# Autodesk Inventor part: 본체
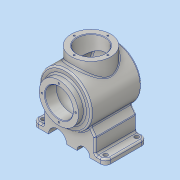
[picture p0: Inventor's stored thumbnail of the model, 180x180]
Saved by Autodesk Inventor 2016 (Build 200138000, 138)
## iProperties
Created: 2018-08
Part Number: 본체
Material: 알루미늄 6061
Document SubType Name: Modeling
Designer: 605-07
Density: 2.7 g/cm^3
Appearance: 알루미늄 - 평지
Author: 605-07
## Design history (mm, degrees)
sketch "스케치1"
  geometry: L1 (70, 40)-(-70, 40); L2 (-70, 40)-(-70, -40); L3 (-70, -40)-(70, -40); L4 (70, -40)-(70, 40); L5 (70, 40)-(-70, -40); L6 (-70, 40)-(70, -40); 1 further point
  constraints: 12 end point, 2 midpoint, 2 parallel, 1 horizontal, 1 perpendicular
  dimensions: "d0" = 140 distance of L1.start L1.end; "d1" = 80 distance of L1.end L2.end
extrude "돌출1" new body sketch "스케치1" distance "d2" = 10; taper "d3" = 0 deg
fillet "모깎기1" dims "d4" = 10
sketch "스케치2"
  geometry: L1 (120, 10)-(0, 10) reference; L2 (10, 10)-(10, 38.563); L3 (-10, 10)-(-10, 0) reference; L4 (110, 10)-(110, 38.563); L5 (130, 0)-(130, 10) reference; L6 (10, 38.563)-(60, 109.97); L7 (110, 38.563)-(60, 109.97); L8 (-10, 0)-(-10, 10) reference; L9 (10, 38.563)-(-10, 10); L10 (110, 38.563)-(130, 10); L11 (10, 10)-(110, 10); 1 further point
  constraints: 14 end point, 3 point on line, 2 collinear, 2 vertical, 1 perpendicular
  dimensions: "d5" = 20 distance between parallel lines of L2 L3; "d6" = 20 distance between parallel lines of L5 L4; "d7" = 35 deg angle of L3 L6; "d8" = 35 deg angle of L5 L7
extrude "돌출2" join sketch "스케치2" distance "d9" = 80; taper "d10" = 0 deg
node "작업 평면1"
sketch "스케치3"
  geometry: C1 r 50 at (60, 82); 1 further point
  constraints: 1 centre point, 1 vertical alignment
  dimensions: "d12" = 82 distance of C1.centre point (60, 0); "d13" = 100 diameter of C1
extrude "돌출3" join sketch "스케치3" distance "d14" = 108; taper "d15" = 0 deg
sketch "스케치4"
  geometry: L1 (32, -60)-(132, -60) reference; L2 (32, 48)-(132, 48) reference; L3 (82, 56)-(82, -60); L4 (82, -60)-(132, -60); L5 (132, -60)-(132, -48.671); A1 r 116 centre (82, 56) between (82, -60) and (132, -48.671); 2 further points
  constraints: 6 end point, 2 midpoint, 2 point on circle, 1 centre point, 1 horizontal, 1 perpendicular, 1 tangent, 1 vertical, 1 vertical alignment
  dimensions: "d16" = 116 radius of A1; "d17" = 50 distance of L3.end L4.end
revolve "회전1" sketch "스케치4" stored, may be unused: angle "d18" = 90 deg
sketch "스케치5"
  geometry: C1 r 50 at (0, 0) reference; C2 r 38 at (0, 0); 1 further point
  constraints: 1 centre point, 1 coincident
  dimensions: "d19" = 76 diameter of C2
extrude "돌출4" join sketch "스케치5" distance "d20" = 12; taper "d21" = 0 deg
sketch "스케치6"
  geometry: L1 (120, 0)-(0, 0) reference; C1 r 17.5 at (37.5, 0); C2 r 12.5 at (87.5, 0); 1 further point
  constraints: 2 centre point, 2 point on line
  dimensions: "d22" = 22.5 distance of point (60, 0) C1.centre; "d23" = 17.5 radius of C1; "d24" = 27.5 distance of C2.centre point (60, 0); "d25" = 12.5 radius of C2
extrude "돌출5" cut sketch "스케치6" stored distance "d26" = 12; taper "d27" = 0 deg
sketch "스케치7"
  geometry: C1 r 38 at (0, 0) reference; C2 r 27 at (0, 0); 1 further point
  constraints: 1 centre point, 1 coincident
  dimensions: "d28" = 54 diameter of C2
extrude "돌출6" cut sketch "스케치7" distance "d29" = 22; taper "d30" = 0 deg
sketch "스케치8"
  geometry: L1 (122, 38)-(82, 38); L2 (82, 38)-(82, -50); L3 (122, -42.163)-(122, 38); L4 (55, 38)-(109, 38) reference; L5 (132, 48)-(132, -48.671) reference; A1 r 116 centre (82, 56) between (32, -48.671) and (132, -48.671) reference; A2 r 106 centre (82, 56) between (82, -50) and (122, -42.163); 1 further point
  constraints: 6 end point, 2 point on circle, 1 centre point, 1 collinear, 1 horizontal, 1 parallel, 1 perpendicular
  dimensions: "d31" = 10 distance between parallel lines of L3 L5; "d32" = 40 distance between parallel lines of L2 L3; "d33" = 10 radial gap between concentric circles of A1 A2
revolve "회전2" sketch "스케치8" stored, may be unused: angle "d34" = 90 deg
node "작업 평면2"
sketch "스케치9"
  geometry: L1 (-50, 48)-(50, 48) reference; C1 r 38 at (0, -2); 1 further point
  constraints: 1 centre point, 1 vertical alignment
  dimensions: "d36" = 50 distance from line of L1 C1.centre; "d37" = 76 diameter of C1
extrude "돌출7" join sketch "스케치9" stored distance "d38" = 22; taper "d39" = 0 deg
sketch "스케치10"
  geometry: C1 r 38 at (0, 0) reference; C2 r 27 at (0, 0); 1 further point
  constraints: 1 centre point, 1 coincident
  dimensions: "d40" = 54 diameter of C2
extrude "돌출8" cut sketch "스케치10" stored distance "d41" = 22; taper "d42" = 0 deg
sketch "스케치11"
  geometry: C1 r 27 at (0, 0) reference; 2 further points
  constraints: 1 vertical alignment
  dimensions: "d43" = 32.5 distance of C1.centre point (0, 32.5)
hole "구멍1" sketch "스케치11" at (0, 32.5) diameter "d44" = 3.242; stored, may be unused: countersink angle "d48" = 90 deg, drill point angle "d50" = 118 deg; dims "d45" = 8, "d46" = 4, "d47" = 2, "d49" = 10
sketch "스케치12"
  geometry: C1 r 27 at (0, 0) reference; 2 further points
  constraints: 1 vertical alignment
  dimensions: "d54" = 32.5 distance of C1.centre point (0, 32.5)
hole "구멍2" sketch "스케치12" at (0, 32.5) diameter "d55" = 3.242; stored, may be unused: countersink angle "d59" = 90 deg, drill point angle "d61" = 118 deg; dims "d56" = 8, "d57" = 4, "d58" = 2, "d60" = 10
fillet "모깎기3" dims "d66" = 3
fillet "모깎기4" dims "d67" = 3
chamfer "모따기1" distance "d68" = 1; stored, may be unused: second distance "d69" = 2, angle "d70" = 45 deg
sketch "스케치15"
  geometry: L1 (-70, 30)-(-67, 30) reference; L2 (70, 30)-(67, 30) reference; L3 (70, -30)-(67, -30) reference; L4 (-60, -40)-(-60, -37) reference; L5 (-70, -30)-(-67, -30) reference; L6 (60, -40)-(60, -37) reference; L7 (60, 40)-(60, 37) reference; L8 (-60, 40)-(-60, 37) reference; A1 r 7 centre (-60, 30) between (-60, 37) and (-67, 30) reference; A2 r 10 centre (-60, 30) between (-60, 40) and (-70, 30) reference; A3 r 7 centre (60, 30) between (67, 30) and (60, 37) reference; A4 r 10 centre (60, 30) between (70, 30) and (60, 40) reference; A5 r 7 centre (60, -30) between (60, -37) and (67, -30) reference; A6 r 10 centre (60, -30) between (60, -40) and (70, -30) reference; A7 r 7 centre (-60, -30) between (-67, -30) and (-60, -37) reference; A8 r 10 centre (-60, -30) between (-70, -30) and (-60, -40) reference; 5 further points
  constraints: 4 coincident
hole "구멍3" sketch "스케치15" at (-60, 30), (-60, -30), (60, -30), (60, 30) diameter "d81" = 8; stored, may be unused: countersink angle "d85" = 90 deg, drill point angle "d87" = 118 deg; dims "d82" = 8, "d83" = 4, "d84" = 2, "d86" = 10
fillet "모깎기5" dims "d88" = 3
fillet "모깎기7" dims "d90" = 3
node "솔리드1"
pattern_circular "원형 패턴1" dims angle "d52" = 360 deg
pattern_circular "원형 패턴2" dims angle "d63" = 360 deg
node "투영된 루프1"
node "투영된 루프2"
node "투영된 루프3"
node "투영된 루프4"
other parameters: "d11" = 8, "d35" = 147
